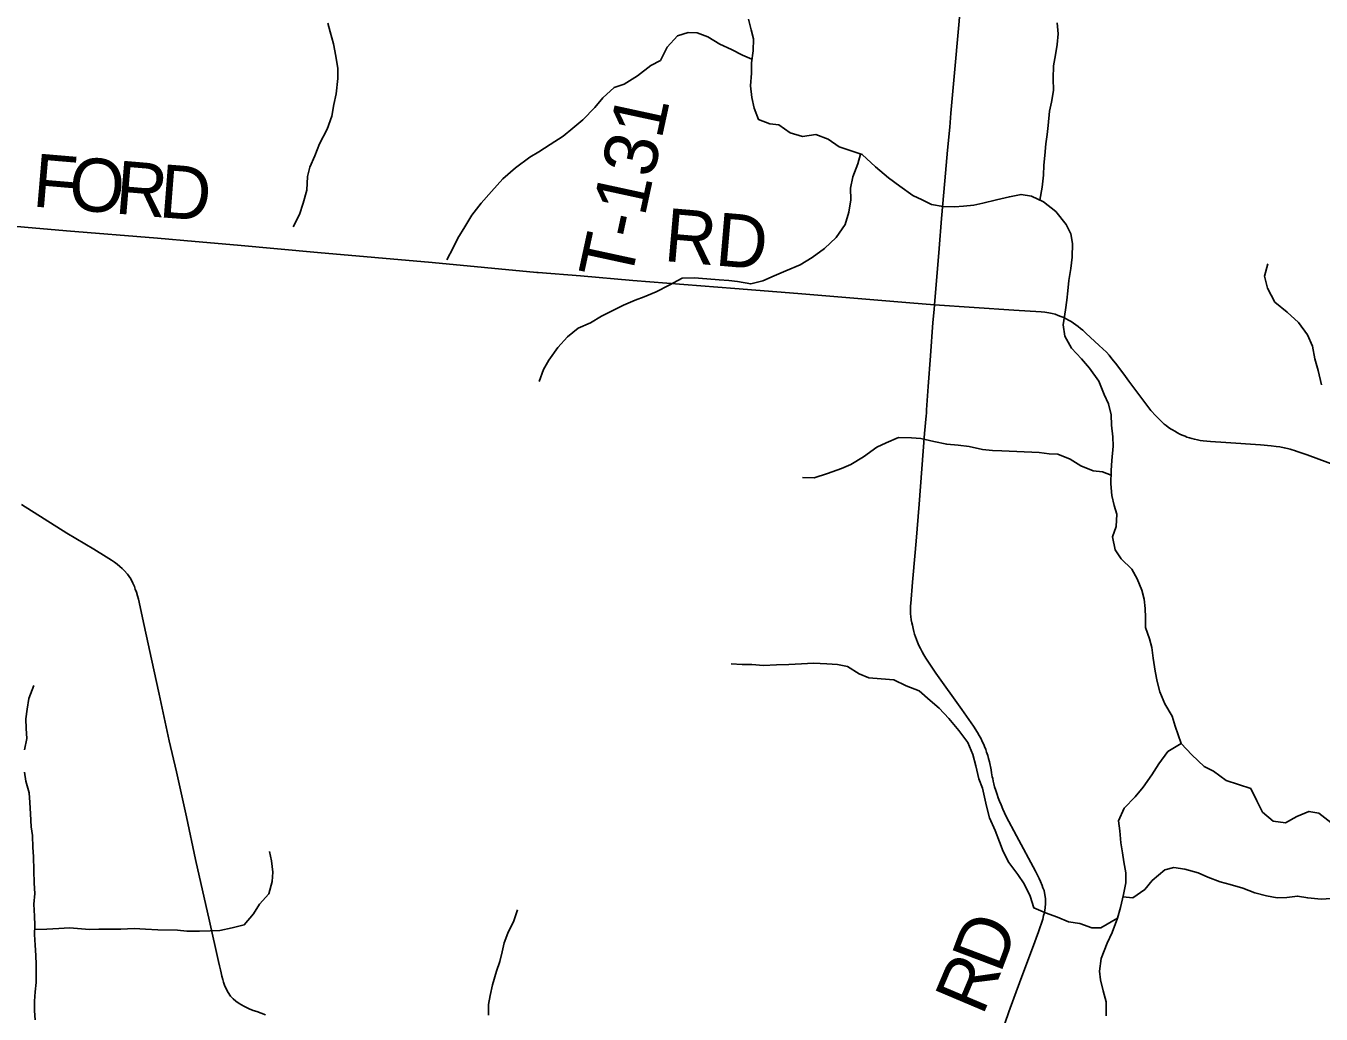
# Model space of a CAD drawing. Extents: x 0 to 48.6, y 0 to 22.
# Drawn here: x 4.141 to 5.524, y 18.56 to 19.616 of the extents above; entities that cross this region are included whole.
import ezdxf

# ---------------------------------------------------------------- set-up
doc = ezdxf.new("R2010")
doc.units = 0
for name, color, linetype in [('GM_X_County_Road', 7, 'Continuous'), ('GM_X_County_Road_Text', 7, 'Continuous'), ('GM_X_Major_River', 7, 'Continuous'), ('GM_X_Minor_River', 7, 'Continuous'), ('GM_X_State_Route', 7, 'Continuous'), ('GM_X_Township_Road', 7, 'Continuous'), ('GM_X_Township_Road_Text', 7, 'Continuous')]:
    doc.layers.add(name, color=color, linetype=linetype)

msp = doc.modelspace()

# ---------------------------------------------------------------- linework, layer by layer
at = {"layer": 'GM_X_County_Road'}
for points in [[(5.1109, 19.3182), (5.1158, 19.3783), (5.1186, 19.4104), (5.1221, 19.4507), (5.1248, 19.4835), (5.1272, 19.5081), (5.1285, 19.523), (5.1315, 19.5583), (5.1373, 19.6214), (5.1395, 19.648), (5.143, 19.6839), (5.1452, 19.7105), (5.1471, 19.7328), (5.149, 19.755), (5.1505, 19.7774), (5.1525, 19.8046), (5.1548, 19.84), (5.1559, 19.8623), (5.1569, 19.8771), (5.1574, 19.8844)], [(5.1813, 18.5368), (5.1903, 18.5626), (5.1956, 18.5772), (5.2042, 18.6004), (5.2155, 18.6306), (5.222, 18.6481), (5.2266, 18.6617), (5.2275, 18.6655), (5.2283, 18.6684), (5.2288, 18.6715), (5.2292, 18.674), (5.2295, 18.6784), (5.2295, 18.6813), (5.2295, 18.6835), (5.2289, 18.6879), (5.2284, 18.69), (5.2279, 18.6922), (5.2268, 18.6952), (5.226, 18.6976), (5.2242, 18.7018), (5.2228, 18.7051), (5.2188, 18.7129), (5.1985, 18.7506), (5.1876, 18.7715), (5.1857, 18.7754), (5.1838, 18.7793), (5.182, 18.7838), (5.1803, 18.7879), (5.179, 18.7915), (5.1778, 18.7948), (5.1764, 18.7993), (5.1752, 18.8031), (5.1744, 18.8064), (5.1737, 18.8091), (5.1731, 18.8119), (5.1727, 18.8139), (5.1719, 18.8179), (5.1713, 18.8212), (5.1696, 18.8298), (5.1687, 18.8333), (5.1678, 18.8365), (5.1666, 18.8402), (5.1657, 18.843), (5.1645, 18.8461), (5.1636, 18.8482), (5.162, 18.8517), (5.1607, 18.8545), (5.1588, 18.8579), (5.157, 18.8611), (5.1527, 18.8679), (5.1403, 18.8858), (5.1125, 18.9247), (5.1074, 18.9321), (5.1044, 18.9364), (5.1018, 18.9406), (5.0995, 18.9443), (5.0978, 18.9475), (5.096, 18.9508), (5.0944, 18.9543), (5.0929, 18.9576), (5.0918, 18.9605), (5.0907, 18.9633), (5.0897, 18.9664), (5.0889, 18.9692), (5.0881, 18.9723), (5.0873, 18.9757), (5.0868, 18.9784), (5.0862, 18.9817), (5.0858, 18.985), (5.0855, 18.9879), (5.0855, 18.9906), (5.0854, 18.9934), (5.0855, 18.9964), (5.0857, 18.9989), (5.0874, 19.0218), (5.0879, 19.0257), (5.0883, 19.0298), (5.0914, 19.0657), (5.0945, 19.1053), (5.1004, 19.1808), (5.102, 19.1997), (5.1023, 19.2025), (5.1025, 19.2058), (5.1041, 19.231), (5.1068, 19.2638), (5.1093, 19.2991), (5.1106, 19.3133), (5.1109, 19.3182)]]:
    msp.add_lwpolyline(points, dxfattribs=at)
at = {"layer": 'GM_X_Major_River'}
for points in [[(5.5343, 18.7649), (5.5213, 18.775), (5.5107, 18.7768), (5.498, 18.7713), (5.4857, 18.7647), (5.4725, 18.7665), (5.4613, 18.7762), (5.4551, 18.7881), (5.4486, 18.8015), (5.4357, 18.8056), (5.4225, 18.81), (5.4087, 18.8198), (5.3989, 18.8249), (5.3859, 18.8373), (5.3744, 18.8493), (5.3602, 18.8409), (5.3504, 18.8278), (5.343, 18.8158), (5.3336, 18.8027), (5.3254, 18.7926), (5.3134, 18.7804), (5.3074, 18.7668), (5.3087, 18.7562), (5.3099, 18.7432), (5.3116, 18.7326), (5.3133, 18.7231), (5.3154, 18.7113), (5.3151, 18.7006), (5.3126, 18.6882), (5.3096, 18.6742), (5.3064, 18.6629)], [(5.3064, 18.6629), (5.3007, 18.6474), (5.2952, 18.6361), (5.2888, 18.6196), (5.287, 18.6063), (5.2883, 18.5968), (5.2911, 18.585), (5.2942, 18.5735), (5.2943, 18.5584)]]:
    msp.add_lwpolyline(points, dxfattribs=at)
at = {"layer": 'GM_X_Minor_River'}
for points in [[(4.463, 19.6192), (4.4655, 19.6097), (4.4692, 19.5971), (4.4716, 19.5838), (4.4737, 19.5705), (4.474, 19.5599), (4.4719, 19.5436), (4.4694, 19.5322), (4.4674, 19.5197), (4.4623, 19.5058), (4.4541, 19.4903), (4.4493, 19.4774), (4.4439, 19.4654), (4.4415, 19.4552), (4.4409, 19.4407), (4.4369, 19.4267), (4.4329, 19.4146), (4.4263, 19.4014)], [(5.3744, 18.8493), (5.3681, 18.868), (5.3648, 18.8787), (5.357, 18.8917), (5.3515, 18.9047), (5.3486, 18.9157), (5.3465, 18.9268), (5.3444, 18.9405), (5.343, 18.9519), (5.3405, 18.9614), (5.3364, 18.9732), (5.3362, 18.9842), (5.3359, 18.9937), (5.3349, 19.0036), (5.3324, 19.0131), (5.3272, 19.0253), (5.3217, 19.0357), (5.3104, 19.0468), (5.3037, 19.0564), (5.3012, 19.0701), (5.3048, 19.0814), (5.3057, 19.0943), (5.3028, 19.1039), (5.3003, 19.1145), (5.2993, 19.1267), (5.2995, 19.1411), (5.3004, 19.1517), (5.3018, 19.1673), (5.3015, 19.1771), (5.2998, 19.1897), (5.2995, 19.2007), (5.2967, 19.2125), (5.2922, 19.2224), (5.2863, 19.2366), (5.2766, 19.2503), (5.268, 19.2603), (5.2572, 19.2719), (5.2501, 19.2845), (5.2484, 19.2966), (5.2509, 19.3129), (5.2522, 19.3232), (5.2534, 19.333), (5.2543, 19.344), (5.2564, 19.3569), (5.2581, 19.369), (5.2583, 19.3835), (5.2565, 19.3941), (5.2517, 19.404), (5.2405, 19.4178), (5.2273, 19.4283), (5.2145, 19.4341), (5.2035, 19.4362), (5.1909, 19.4337), (5.1772, 19.4304), (5.1624, 19.4268), (5.1528, 19.4247), (5.1418, 19.4237), (5.1323, 19.4227), (5.1202, 19.4232), (5.1076, 19.4253), (5.0978, 19.4303), (5.088, 19.435), (5.0741, 19.4451), (5.0617, 19.4539), (5.0478, 19.4655), (5.0339, 19.4786), (5.0199, 19.4833), (5.0093, 19.4869), (4.9973, 19.495), (4.9841, 19.5001), (4.97, 19.498), (4.9567, 19.502), (4.9447, 19.5105), (4.9352, 19.5114), (4.9231, 19.5161), (4.9183, 19.5283), (4.9158, 19.5397), (4.9145, 19.5523), (4.9154, 19.5656), (4.9156, 19.5769), (4.9172, 19.5894), (4.9178, 19.6023), (4.9153, 19.6119), (4.9124, 19.6233)], [(5.2235, 19.43), (5.226, 19.4438), (5.2273, 19.4567), (5.2278, 19.4674), (5.2287, 19.4776), (5.2297, 19.4901), (5.2313, 19.5003), (5.2322, 19.5098), (5.2339, 19.525), (5.236, 19.5348), (5.238, 19.5473), (5.2378, 19.5599), (5.238, 19.5735), (5.24, 19.5853), (5.2421, 19.5962), (5.243, 19.6076), (5.242, 19.6194)], [(4.916, 19.5805), (4.9058, 19.585), (4.8941, 19.5909), (4.8816, 19.5967), (4.8688, 19.6045), (4.8575, 19.6088), (4.848, 19.6093), (4.8366, 19.6057), (4.8254, 19.5933), (4.8184, 19.5793), (4.808, 19.5738), (4.7938, 19.563), (4.7797, 19.554), (4.769, 19.5504), (4.7567, 19.5395), (4.7482, 19.529), (4.7355, 19.5159), (4.7247, 19.5069), (4.7144, 19.4983), (4.7006, 19.4894), (4.6883, 19.4816), (4.6787, 19.476), (4.6634, 19.4644), (4.6499, 19.4528), (4.638, 19.4393), (4.6268, 19.4269), (4.6171, 19.4138), (4.6094, 19.4014), (4.602, 19.3893), (4.5969, 19.3791), (4.5903, 19.3663)], [(5.032, 19.4793), (5.0292, 19.4688), (5.0237, 19.4548), (5.0213, 19.4427), (5.0215, 19.4302), (5.0194, 19.4173), (5.0155, 19.4041), (5.0058, 19.3901), (4.9935, 19.3785), (4.9804, 19.3688), (4.9674, 19.361), (4.9521, 19.3544), (4.9399, 19.3492), (4.9277, 19.3437), (4.9147, 19.3405), (4.9007, 19.3429), (4.8912, 19.3442), (4.881, 19.3447), (4.8677, 19.346), (4.8544, 19.3469), (4.8415, 19.3467), (4.8277, 19.3393), (4.8136, 19.3319), (4.801, 19.3267), (4.7914, 19.3231), (4.7788, 19.3179), (4.7654, 19.3109), (4.7555, 19.3061), (4.7436, 19.299), (4.7303, 19.2931), (4.7191, 19.2838), (4.7087, 19.2725), (4.699, 19.259), (4.6936, 19.2492), (4.6889, 19.2363)], [(5.5241, 19.2327), (5.5205, 19.2479), (5.5172, 19.2605), (5.5147, 19.2738), (5.5092, 19.2861), (5.4995, 19.2991), (5.4875, 19.3103), (5.4743, 19.3211), (5.4665, 19.336), (5.4633, 19.3489), (5.4669, 19.3621)], [(5.2995, 19.1362), (5.2904, 19.1397), (5.2805, 19.1406), (5.2673, 19.1461), (5.256, 19.1531), (5.2428, 19.1585), (5.2333, 19.159), (5.2227, 19.1603), (5.1828, 19.162), (5.1729, 19.1625), (5.1623, 19.1634), (5.1479, 19.1666), (5.1362, 19.1683), (5.124, 19.1692), (5.1104, 19.172), (5.0964, 19.1752), (5.0865, 19.1761), (5.0725, 19.1763), (5.0595, 19.1708), (5.0495, 19.166), (5.035, 19.1559), (5.0216, 19.1477), (5.0116, 19.1433), (4.9968, 19.1378), (4.9826, 19.1334), (4.9701, 19.1336)], [(5.3064, 18.6629), (5.2885, 18.6523), (5.279, 18.6524), (5.2662, 18.6571), (5.254, 18.6588), (5.2423, 18.6639), (5.2295, 18.6686), (5.217, 18.6737), (5.213, 18.6863), (5.2067, 18.6993), (5.2, 18.7096), (5.1903, 18.7223), (5.1844, 18.7341), (5.1803, 18.7444), (5.1756, 18.7563), (5.1697, 18.77), (5.1664, 18.7826), (5.1621, 18.8016), (5.1584, 18.8115), (5.1552, 18.8256), (5.1519, 18.8378), (5.1464, 18.8504), (5.1371, 18.8634), (5.1262, 18.8761), (5.1161, 18.8872), (5.1064, 18.8953), (5.0947, 18.9057), (5.0807, 18.9109), (5.0675, 18.9175), (5.0539, 18.9184), (5.041, 18.9197), (5.0304, 18.924), (5.018, 18.9318), (5.0074, 18.9338), (4.996, 18.9347), (4.9819, 18.9353), (4.969, 18.9347), (4.9553, 18.9337), (4.9424, 18.9335), (4.9283, 18.9326), (4.9158, 18.9339), (4.9056, 18.934), (4.8938, 18.9345)], [(4.1394, 18.8426), (4.1418, 18.8547), (4.1412, 18.8653), (4.1406, 18.8756), (4.1422, 18.8862), (4.1439, 18.8976), (4.1494, 18.9115)], [(4.1507, 18.5543), (4.1501, 18.5638), (4.1499, 18.574), (4.1508, 18.5839), (4.1516, 18.5941), (4.1519, 18.6131), (4.1513, 18.623), (4.1507, 18.634), (4.15, 18.6454), (4.1502, 18.6553), (4.1499, 18.6648), (4.1493, 18.6777), (4.1502, 18.6891), (4.1496, 18.7001), (4.1491, 18.7138), (4.1489, 18.7286), (4.1482, 18.7384), (4.1477, 18.751), (4.1463, 18.7605), (4.1457, 18.7742), (4.1451, 18.7863), (4.1441, 18.7966), (4.1408, 18.8091), (4.1394, 18.8187)], [(4.1501, 18.6507), (4.163, 18.6509), (4.176, 18.6519), (4.1874, 18.6525), (4.2086, 18.6507), (4.2185, 18.651), (4.231, 18.6512), (4.242, 18.651), (4.2565, 18.6516), (4.2686, 18.6511), (4.2815, 18.6502), (4.3028, 18.6499), (4.3127, 18.649), (4.326, 18.6488), (4.3374, 18.6491), (4.348, 18.6497), (4.361, 18.6525), (4.3739, 18.6558), (4.3839, 18.6674), (4.3902, 18.6776), (4.4002, 18.6889), (4.4038, 18.7021), (4.4043, 18.712), (4.4029, 18.7241), (4.4008, 18.734)], [(5.3121, 18.6857), (5.3227, 18.6845), (5.3354, 18.6934), (5.3435, 18.7032), (5.3569, 18.7144), (5.3665, 18.717), (5.3782, 18.7153), (5.3926, 18.7113), (5.4028, 18.7066), (5.416, 18.7015), (5.4266, 18.6987), (5.4402, 18.6947), (5.4531, 18.69), (5.4656, 18.6868), (5.4769, 18.6844), (5.4872, 18.685), (5.4986, 18.6864), (5.5096, 18.6844), (5.5237, 18.683), (5.54, 18.6843)], [(4.6347, 18.559), (4.6349, 18.5704), (4.6365, 18.5803), (4.6389, 18.5916), (4.6433, 18.606), (4.6469, 18.6166), (4.6493, 18.6268), (4.6513, 18.6366), (4.6553, 18.6468), (4.6619, 18.66), (4.6658, 18.6717)]]:
    msp.add_lwpolyline(points, dxfattribs=at)
at = {"layer": 'GM_X_State_Route'}
msp.add_lwpolyline([(4.3965, 18.5594), (4.392, 18.5611), (4.3872, 18.5629), (4.3836, 18.5642), (4.379, 18.566), (4.3762, 18.5674), (4.3734, 18.5687), (4.3685, 18.5716), (4.3649, 18.5742), (4.362, 18.5767), (4.3594, 18.5795), (4.3569, 18.5832), (4.3547, 18.5871), (4.3529, 18.5911), (4.3518, 18.5943), (4.351, 18.5971), (4.3501, 18.6008), (4.3492, 18.6044), (4.3484, 18.6074), (4.3475, 18.6117), (4.3464, 18.6164), (4.3367, 18.6595), (4.322, 18.7256), (4.3121, 18.7711), (4.3014, 18.819), (4.2938, 18.8523), (4.283, 18.9021), (4.2773, 18.9282), (4.2671, 18.9756), (4.2609, 19.0035), (4.2599, 19.0073), (4.2588, 19.0112), (4.2576, 19.0144), (4.2567, 19.017), (4.255, 19.0209), (4.2527, 19.0252), (4.2509, 19.0278), (4.2492, 19.0302), (4.2456, 19.0344), (4.2435, 19.0365), (4.241, 19.0387), (4.2383, 19.0409), (4.2354, 19.043), (4.2323, 19.0452), (4.2266, 19.0488), (4.2133, 19.0569), (4.1846, 19.0743), (4.1604, 19.0894), (4.1362, 19.1047)], dxfattribs=at)
at = {"layer": 'GM_X_Township_Road'}
for points in [[(3.4237, 19.4632), (3.4298, 19.4628), (3.4858, 19.4592), (3.6097, 19.4486), (3.6567, 19.4445), (3.6982, 19.4408), (3.8734, 19.4248), (3.9644, 19.417), (4.0125, 19.4121), (4.1842, 19.3971), (4.2813, 19.3892), (4.3215, 19.3858), (4.3667, 19.3818), (4.4521, 19.374), (4.5746, 19.3634), (4.6862, 19.3527), (4.6878, 19.3526)], [(4.6878, 19.3526), (4.733, 19.349), (4.7889, 19.3442), (4.8977, 19.3355), (4.9652, 19.3303), (5.0847, 19.3204), (5.1109, 19.3182)], [(5.1109, 19.3182), (5.1956, 19.3125), (5.2247, 19.3106), (5.2288, 19.3102), (5.2329, 19.3097), (5.2365, 19.3089), (5.2397, 19.3081), (5.2431, 19.3069), (5.246, 19.3057), (5.2489, 19.3045), (5.2515, 19.3032), (5.254, 19.3019), (5.2568, 19.3002), (5.2594, 19.2987), (5.2618, 19.2969), (5.2645, 19.295), (5.2669, 19.293), (5.2693, 19.291), (5.2726, 19.2879), (5.2868, 19.2748), (5.2948, 19.2674), (5.2975, 19.2643), (5.3004, 19.2606), (5.3041, 19.2559), (5.3132, 19.2442), (5.3184, 19.2366), (5.3355, 19.2137), (5.342, 19.2054), (5.3473, 19.1994), (5.3525, 19.1941), (5.3561, 19.1908), (5.3584, 19.1891), (5.3605, 19.1875), (5.3631, 19.1858), (5.3652, 19.1845), (5.3677, 19.183), (5.3705, 19.1814), (5.3731, 19.1801), (5.3754, 19.1789), (5.3785, 19.1777), (5.3805, 19.1768), (5.3832, 19.176), (5.3858, 19.1752), (5.3885, 19.1745), (5.3918, 19.1738), (5.3946, 19.1733), (5.3978, 19.1728), (5.4017, 19.1725), (5.4058, 19.1721), (5.4219, 19.1711), (5.4591, 19.1687), (5.4703, 19.1676), (5.4757, 19.1668), (5.4796, 19.1663), (5.4845, 19.1654), (5.4878, 19.1646), (5.4906, 19.1639), (5.4929, 19.1632), (5.4954, 19.1624), (5.4982, 19.1614), (5.5089, 19.1577), (5.5654, 19.1368)]]:
    msp.add_lwpolyline(points, dxfattribs=at)

# ---------------------------------------------------------------- texts
at = {"layer": 'GM_X_County_Road_Text'}
for s, rotation, p in [('D', 69.2624, (5.1813, 18.6026)), ('R', 67.0469, (5.1622, 18.5575))]:
    msp.add_text(s, height=0.0568, rotation=rotation, dxfattribs=at).set_placement(p)
at = {"layer": 'GM_X_Township_Road_Text'}
for s, height, rotation, p in [('T-131', 0.05682, 77.7706, (4.7863, 19.3412)), ('F', 0.0568, 355.1476, (4.1468, 19.4234)), ('O', 0.0568, 355.1456, (4.185, 19.4202)), ('R', 0.0568, 355.1465, (4.2348, 19.4159)), ('D', 0.0568, 355.5745, (4.2818, 19.4119)), ('RD', 0.05682, 355.0719, (4.821, 19.3651))]:
    msp.add_text(s, height=height, rotation=rotation, dxfattribs=at).set_placement(p)

doc.saveas('drawing.dxf')
